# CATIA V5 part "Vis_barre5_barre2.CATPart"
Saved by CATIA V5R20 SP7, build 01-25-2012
Part number: Vis_barre5_barre2
Bounding box of the stored display mesh (mm): x -2.5 to 8.5, y 26.955 to 28.954, z -0.048 to 1.952
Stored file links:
  J:\IFMA\IAO\système avant mef\Vis_barre5_barre2.CATPart
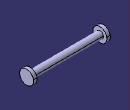
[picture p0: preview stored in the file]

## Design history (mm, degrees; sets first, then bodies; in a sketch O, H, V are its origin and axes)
Body1 (main body)
  Line1: stored without definition
  Point1 "point_Bsecond": stored without definition
  Plane1: type Normal, Curve Line1, RefPoint Point1
  Line2 "axe_liaison_barre2_barre1": stored without definition
  DatumCurve1
  Line3 "barre_5": stored without definition
  Line4 "axe_liaison_barre2_barre1": stored without definition
  Line5 "axe_liaison_barre2_barre1": stored without definition
  DatumCurve2
  Line6 "axe_liaison_barre2_barre1": stored without definition
  Line7: stored without definition
  Sketch1 on Plane1, origin (0, 3.1864, 9.3725), H (-1, 0, 0), V (0, -0.9468, 0.3219)
    point P1 (2.5, -26.1604)
    line L1 (2.5, -26.1604) -> (2.5, -25.1604)
    line L2 (2.5, -25.1604) -> (2, -25.1604)
    line L3 (2, -25.1604) -> (2, -25.6604)
    line L4 (2, -25.6604) -> (-8, -25.6604)
    line L5 (-8, -25.6604) -> (-8, -25.1604)
    point P6 (-8, -25.1604)
    line L6 (-8, -25.1604) -> (-8.5, -25.1604)
    line L7 (-8.5, -25.1604) -> (-8.5, -26.1604)
    point P8 (-8.5, -26.1604)
    reference projected line E1 (0, -26.1604) -> (-20, -26.1604) from Line2
    reference projected line E2 (-8, -25.1604) -> (-8, -16.486) from edge of DatumCurve1
    reference projected line E3 (2, -17.0421) -> (2, -26.1604) from Line3
    reference projected line E4 (0, -26.1604) -> (-20, -26.1604) from Line4
    reference projected line E5 (0, -26.1604) -> (-20, -26.1604) from Line5
    reference projected line E6 (2, -27.1604) -> (2, -25.8385) from edge of DatumCurve2
    reference projected line E7 (0, -26.1604) -> (-20, -26.1604) from Line6
    distance L6 E4 = 1
    distance L4 E5 = 0.5
    distance L1 E6 = 0.5
    distance L7 L5 = 0.5
    vertical: L1 V, L3 V, L5 V, L7 V
    horizontal: L2 H, L4 H, L6 H
    coincidence: P6 L2, P8 E1, L5 E2, L3 E3, E7 P1
  Shaft1: profile Sketch1, axis Line7, angle 360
